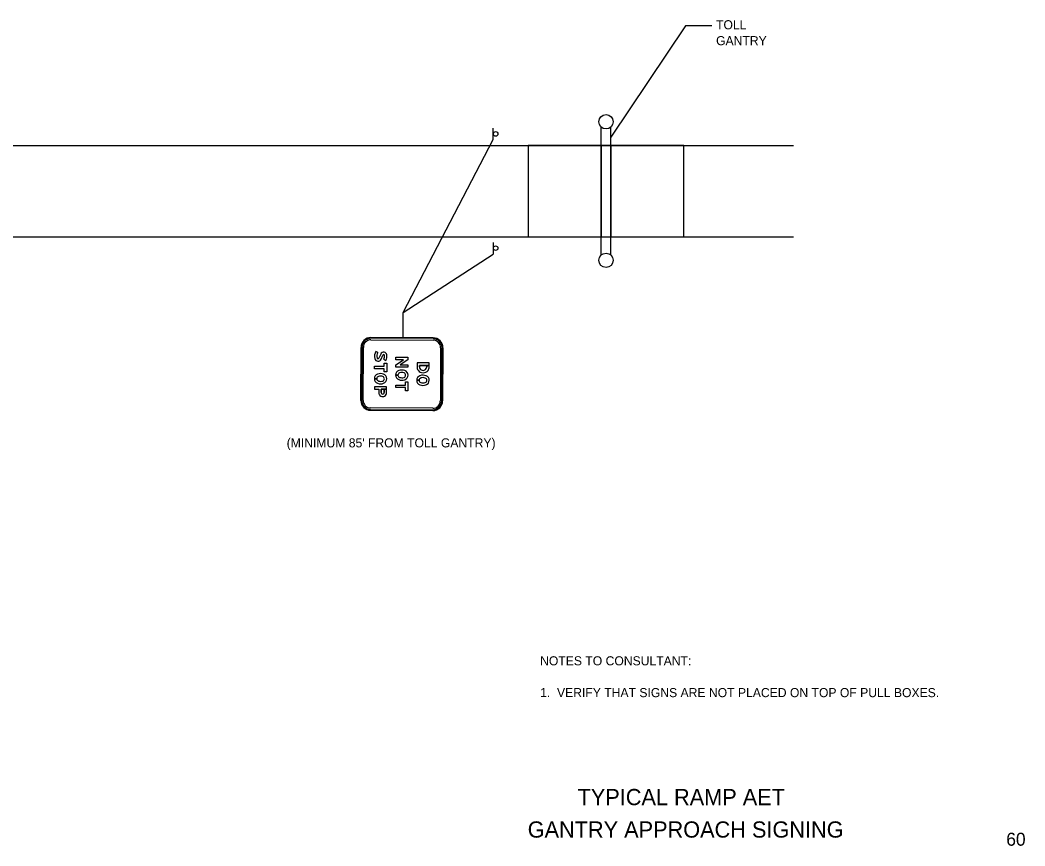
# Model space of a CAD drawing. Extents: x 2147219 to 2148785, y 2147055 to 2147716.
# Drawn here: x 2148011 to 2148785, y 2147080 to 2147716 of the extents above; entities that cross this region are included whole.
import ezdxf

# ---------------------------------------------------------------- set-up
doc = ezdxf.new("R2010")
doc.units = 0
for name, color, linetype in [('4', 7, 'Continuous'), ('5', 7, 'Continuous'), ('Default', 7, 'Continuous'), ('LeaderLine_dp', 7, 'Continuous'), ('RoadwayMisc', 7, 'Continuous'), ('SignPanel', 7, 'Continuous'), ('SignSupport', 7, 'Continuous'), ('TextMisc', 7, 'Continuous'), ('TextShtNo', 7, 'Continuous'), ('TollReader', 7, 'Continuous')]:
    doc.layers.add(name, color=color, linetype=linetype)

msp = doc.modelspace()

# ---------------------------------------------------------------- linework, layer by layer
at = {"layer": '4'}
msp.add_line((2148523.89, 2147711.93), (2148466.13, 2147626.09), dxfattribs=at)
at = {"layer": 'Default'}
msp.add_line((2148543.93, 2147711.93), (2148523.89, 2147711.93), dxfattribs=at)
at = {"layer": 'LeaderLine_dp'}
for p, q in [((2148306.25, 2147490.99), (2148375.7, 2147624.25)), ((2148306.25, 2147490.99), (2148375.7, 2147536.1)), ((2148306.15, 2147471.79), (2148306.25, 2147490.99))]:
    msp.add_line(p, q, dxfattribs=at)
at = {"layer": 'RoadwayMisc'}
for p, q in [((2147481.92, 2147619.77), (2148606.92, 2147619.77)), ((2148458.91, 2147619.77), (2148402.52, 2147619.77)), ((2148402.52, 2147619.77), (2148402.52, 2147549.46)), ((2148458.91, 2147549.46), (2148458.91, 2147619.77)), ((2148466.13, 2147619.77), (2148458.91, 2147619.77)), ((2148458.91, 2147619.77), (2148458.91, 2147549.46)), ((2148522.52, 2147619.77), (2148466.13, 2147619.77)), ((2148466.13, 2147619.77), (2148466.13, 2147549.46)), ((2148466.13, 2147549.46), (2148466.13, 2147619.77)), ((2148522.52, 2147549.46), (2148522.52, 2147619.77)), ((2147481.92, 2147549.46), (2148606.92, 2147549.46)), ((2148402.52, 2147549.46), (2148458.91, 2147549.46)), ((2148458.91, 2147549.46), (2148466.13, 2147549.46)), ((2148466.13, 2147549.46), (2148522.52, 2147549.46))]:
    msp.add_line(p, q, dxfattribs=at)
at = {"layer": 'SignPanel'}
for p, q in [((2148329.31, 2147471.48), (2148281.46, 2147471.71)), ((2148329.31, 2147471.48), (2148281.46, 2147471.71)), ((2148281.46, 2147471.59), (2148329.31, 2147471.36)), ((2148273.84, 2147464.16), (2148273.64, 2147423.32)), ((2148273.84, 2147464.16), (2148273.64, 2147423.32)), ((2148273.76, 2147423.32), (2148273.96, 2147464.16)), ((2148273.84, 2147464.16), (2148273.96, 2147464.16)), ((2148273.96, 2147464.16), (2148273.84, 2147464.16)), ((2148274.42, 2147464.15), (2148274.23, 2147423.31)), ((2148274.42, 2147464.16), (2148275.59, 2147464.16)), ((2148275.59, 2147464.14), (2148274.42, 2147464.15)), ((2148275.39, 2147423.31), (2148275.59, 2147464.14)), ((2148281.45, 2147469.96), (2148329.3, 2147469.73)), ((2148329.3, 2147470.9), (2148281.46, 2147471.13)), ((2148335.1, 2147463.87), (2148334.91, 2147423.02)), ((2148336.07, 2147423.02), (2148336.27, 2147463.86)), ((2148336.74, 2147463.86), (2148336.54, 2147423.01)), ((2148336.66, 2147423.01), (2148336.85, 2147463.86)), ((2148336.66, 2147423.01), (2148336.85, 2147463.86)), ((2148286.82, 2147460.12), (2148285.23, 2147461.09)), ((2148286.82, 2147460.12), (2148285.23, 2147461.09)), ((2148286.82, 2147460.12), (2148285.23, 2147461.09)), ((2148288.99, 2147458.99), (2148287.59, 2147455.83)), ((2148288.99, 2147458.99), (2148287.59, 2147455.83)), ((2148288.99, 2147458.99), (2148287.59, 2147455.83)), ((2148289.29, 2147455.08), (2148290.7, 2147458.23)), ((2148289.29, 2147455.08), (2148290.7, 2147458.23)), ((2148289.29, 2147455.08), (2148290.7, 2147458.23)), ((2148291.32, 2147454.99), (2148292.97, 2147454.1)), ((2148291.32, 2147454.99), (2148292.97, 2147454.1)), ((2148291.32, 2147454.99), (2148292.97, 2147454.1)), ((2148316.94, 2147449.12), (2148316.94, 2147449.12)), ((2148318.81, 2147449.11), (2148318.81, 2147450.3)), ((2148318.81, 2147449.11), (2148318.81, 2147450.3)), ((2148318.81, 2147449.11), (2148318.81, 2147449.11)), ((2148300.41, 2147442.82), (2148302.28, 2147442.81)), ((2148302.28, 2147442.81), (2148300.41, 2147442.82)), ((2148300.41, 2147442.82), (2148302.28, 2147442.81)), ((2148302.28, 2147442.81), (2148300.41, 2147442.82)), ((2148284.07, 2147440), (2148285.93, 2147440)), ((2148285.93, 2147440), (2148284.07, 2147440)), ((2148284.07, 2147440), (2148285.93, 2147440)), ((2148285.93, 2147440), (2148284.07, 2147440)), ((2148316.73, 2147438.82), (2148318.6, 2147438.81)), ((2148318.6, 2147438.81), (2148316.73, 2147438.82)), ((2148316.73, 2147438.82), (2148318.6, 2147438.81)), ((2148318.6, 2147438.81), (2148316.73, 2147438.82)), ((2148287.54, 2147431.99), (2148287.53, 2147429.22)), ((2148289.41, 2147431.98), (2148289.4, 2147429.31)), ((2148329.05, 2147417.22), (2148281.2, 2147417.45)), ((2148281.19, 2147416.28), (2148329.04, 2147416.05)), ((2148329.04, 2147415.58), (2148281.19, 2147415.81)), ((2148281.19, 2147415.7), (2148329.04, 2147415.47)), ((2148281.19, 2147415.7), (2148329.04, 2147415.47))]:
    msp.add_line(p, q, dxfattribs=at)
for points in [[(2148309.98, 2147456.49), (2148309.97, 2147454.63), (2148304.07, 2147450.83), (2148309.95, 2147450.8), (2148309.94, 2147448.93), (2148300.61, 2147448.98), (2148300.62, 2147450.82), (2148306.55, 2147454.64), (2148300.63, 2147454.67), (2148300.64, 2147456.54)], [(2148309.98, 2147456.49), (2148309.97, 2147454.63), (2148304.07, 2147450.83), (2148309.95, 2147450.8), (2148309.94, 2147448.93), (2148300.61, 2147448.98), (2148300.62, 2147450.82), (2148306.55, 2147454.64), (2148300.63, 2147454.67), (2148300.64, 2147456.54)], [(2148309.98, 2147456.49), (2148309.97, 2147454.63), (2148304.07, 2147450.83), (2148309.95, 2147450.8), (2148309.94, 2147448.93), (2148300.61, 2147448.98), (2148300.62, 2147450.82), (2148306.55, 2147454.64), (2148300.63, 2147454.67), (2148300.64, 2147456.54)], [(2148284.27, 2147447.75), (2148284.28, 2147449.62), (2148291.74, 2147449.58), (2148291.76, 2147452.1), (2148293.62, 2147452.09), (2148293.59, 2147445.19), (2148291.72, 2147445.19), (2148291.73, 2147447.71)], [(2148284.27, 2147447.75), (2148284.28, 2147449.62), (2148291.74, 2147449.58), (2148291.76, 2147452.1), (2148293.62, 2147452.09), (2148293.59, 2147445.19), (2148291.72, 2147445.19), (2148291.73, 2147447.71)], [(2148284.27, 2147447.75), (2148284.28, 2147449.62), (2148291.74, 2147449.58), (2148291.76, 2147452.1), (2148293.62, 2147452.09), (2148293.59, 2147445.19), (2148291.72, 2147445.19), (2148291.73, 2147447.71)], [(2148300.53, 2147433.2), (2148300.54, 2147435.07), (2148308.01, 2147435.04), (2148308.02, 2147437.56), (2148309.89, 2147437.55), (2148309.85, 2147430.64), (2148307.99, 2147430.65), (2148308, 2147433.17)], [(2148300.53, 2147433.2), (2148300.54, 2147435.07), (2148308.01, 2147435.04), (2148308.02, 2147437.56), (2148309.89, 2147437.55), (2148309.85, 2147430.64), (2148307.99, 2147430.65), (2148308, 2147433.17)], [(2148300.53, 2147433.2), (2148300.54, 2147435.07), (2148308.01, 2147435.04), (2148308.02, 2147437.56), (2148309.89, 2147437.55), (2148309.85, 2147430.64), (2148307.99, 2147430.65), (2148308, 2147433.17)]]:
    msp.add_lwpolyline(points, close=True, dxfattribs=at)
for points in [[(2148326.27, 2147449.07), (2148326.29, 2147452.12), (2148316.96, 2147452.17), (2148316.94, 2147449.12)], [(2148318.81, 2147450.3), (2148326.28, 2147450.27), (2148326.29, 2147452.12), (2148316.96, 2147452.17), (2148316.94, 2147449.12)], [(2148318.81, 2147450.3), (2148326.28, 2147450.27), (2148326.29, 2147452.12), (2148316.96, 2147452.17), (2148316.94, 2147449.12)], [(2148324.41, 2147449.08), (2148324.41, 2147450.28), (2148318.81, 2147450.3), (2148318.81, 2147449.11)], [(2148326.27, 2147449.07), (2148326.28, 2147450.27), (2148324.41, 2147450.28), (2148324.41, 2147449.08)], [(2148326.27, 2147449.07), (2148326.28, 2147450.27), (2148324.41, 2147450.28), (2148324.41, 2147449.08)], [(2148293.51, 2147429.19), (2148293.53, 2147433.8), (2148284.2, 2147433.84), (2148284.19, 2147432), (2148287.54, 2147431.99)], [(2148293.53, 2147433.8), (2148284.2, 2147433.84), (2148284.19, 2147432), (2148287.54, 2147431.99), (2148287.53, 2147429.22)], [(2148293.53, 2147433.8), (2148284.2, 2147433.84), (2148284.19, 2147432), (2148287.54, 2147431.99), (2148287.53, 2147429.22)], [(2148289.4, 2147429.31), (2148289.41, 2147431.98), (2148293.53, 2147431.96), (2148293.53, 2147433.8)], [(2148289.4, 2147429.31), (2148289.41, 2147431.98), (2148293.53, 2147431.96), (2148293.53, 2147433.8)], [(2148291.65, 2147429.29), (2148291.66, 2147431.97), (2148289.41, 2147431.98)], [(2148293.51, 2147429.19), (2148293.53, 2147431.96), (2148291.66, 2147431.97), (2148291.65, 2147429.29)], [(2148293.51, 2147429.19), (2148293.53, 2147431.96), (2148291.66, 2147431.97), (2148291.65, 2147429.29)]]:
    msp.add_lwpolyline(points, dxfattribs=at)
for centre, radius, start, end in [((2148281.42, 2147464.13), 7.58, 89.72459, 179.72459), ((2148281.42, 2147464.13), 7.58, 89.72459, 179.72459), ((2148281.42, 2147464.13), 7.47, 89.72459, 179.72459), ((2148281.42, 2147464.13), 7, 89.72459, 179.72459), ((2148281.42, 2147464.13), 5.83, 89.72459, 179.72459), ((2148329.27, 2147463.9), 7, 359.72459, 89.72459), ((2148329.27, 2147463.9), 5.83, 359.72459, 89.72459), ((2148329.27, 2147463.9), 7.58, 359.72459, 89.72459), ((2148329.27, 2147463.9), 7.58, 359.72459, 89.72459), ((2148329.27, 2147463.9), 7.47, 359.72459, 89.72459), ((2148291.43, 2147457.28), 7.28, 148.44393, 194.20211), ((2148291.43, 2147457.28), 7.28, 148.44393, 194.20211), ((2148291.43, 2147457.28), 7.28, 148.44393, 194.20211), ((2148291.43, 2147457.28), 5.41, 148.44392, 194.2021), ((2148291.43, 2147457.28), 5.41, 148.44392, 194.2021), ((2148291.43, 2147457.28), 5.41, 148.44392, 194.2021), ((2148291.25, 2147457.98), 2.47, 9.21225, 156.04888), ((2148291.25, 2147457.98), 2.47, 9.21225, 156.04888), ((2148291.25, 2147457.98), 2.47, 9.21225, 156.04888), ((2148291.25, 2147457.98), 0.607, 9.21225, 156.04888), ((2148291.25, 2147457.98), 0.607, 9.21225, 156.04888), ((2148291.25, 2147457.98), 0.607, 9.21225, 156.04888), ((2148287.06, 2147457.3), 4.85, 331.54595, 9.21225), ((2148287.06, 2147457.3), 4.85, 331.54595, 9.21225), ((2148287.06, 2147457.3), 4.85, 331.54595, 9.21225), ((2148287.06, 2147457.3), 6.72, 331.54595, 9.21225), ((2148287.06, 2147457.3), 6.72, 331.54595, 9.21225), ((2148287.06, 2147457.3), 6.72, 331.54595, 9.21225), ((2148286.91, 2147456.14), 2.61, 194.2021, 336.04888), ((2148286.91, 2147456.14), 2.61, 194.2021, 336.04888), ((2148286.91, 2147456.14), 2.61, 194.2021, 336.04888), ((2148286.91, 2147456.14), 0.747, 194.2021, 336.04888), ((2148286.91, 2147456.14), 0.747, 194.2021, 336.04888), ((2148286.91, 2147456.14), 0.747, 194.2021, 336.04888), ((2148304.15, 2147442.8), 3.73, 109.33085, 250.11834), ((2148304.15, 2147442.8), 3.73, 109.33085, 179.72459), ((2148304.15, 2147442.8), 3.73, 109.33085, 179.72459), ((2148304.15, 2147442.8), 3.73, 179.73175, 250.11834), ((2148304.15, 2147442.8), 3.73, 179.73175, 250.11834), ((2148304.15, 2147442.8), 1.87, 109.33085, 250.11834), ((2148304.15, 2147442.8), 1.87, 109.33085, 179.72459), ((2148304.15, 2147442.8), 1.87, 109.33085, 179.72459), ((2148304.15, 2147442.8), 1.87, 179.73892, 250.11834), ((2148304.15, 2147442.8), 1.87, 179.73892, 250.11834), ((2148305.21, 2147439.76), 6.95, 70.11834, 109.33084), ((2148305.21, 2147439.76), 6.95, 70.11834, 109.33085), ((2148305.21, 2147439.76), 6.95, 70.11834, 109.33085), ((2148305.24, 2147445.83), 5.09, 250.11834, 289.33084), ((2148305.24, 2147445.83), 5.09, 250.11834, 289.33084), ((2148305.24, 2147445.83), 5.09, 250.11834, 289.33084), ((2148305.21, 2147439.76), 5.09, 70.11834, 109.33084), ((2148305.21, 2147439.76), 5.09, 70.11834, 109.33084), ((2148305.21, 2147439.76), 5.09, 70.11834, 109.33084), ((2148306.31, 2147442.79), 1.87, 289.33085, 70.11834), ((2148306.31, 2147442.79), 1.87, 289.33085, 70.11834), ((2148306.31, 2147442.79), 1.87, 289.33085, 70.11834), ((2148306.31, 2147442.79), 3.73, 289.33085, 70.11834), ((2148306.31, 2147442.79), 3.73, 289.33084, 70.11834), ((2148306.31, 2147442.79), 3.73, 289.33084, 70.11834), ((2148305.24, 2147445.83), 6.95, 250.11834, 289.33084), ((2148305.24, 2147445.83), 6.95, 250.11834, 289.33085), ((2148305.24, 2147445.83), 6.95, 250.11834, 289.33085), ((2148281.23, 2147423.28), 7.58, 179.72459, 269.72459), ((2148281.23, 2147423.28), 7.58, 179.72459, 269.72459), ((2148281.23, 2147423.28), 7.47, 179.72459, 269.72459), ((2148281.23, 2147423.28), 7, 179.72459, 269.72459), ((2148281.23, 2147423.28), 5.83, 179.72459, 269.72459), ((2148329.07, 2147423.05), 7, 269.72459, 359.72459), ((2148329.07, 2147423.05), 7.58, 269.72459, 359.72459), ((2148329.07, 2147423.05), 7.47, 269.72459, 359.72459), ((2148329.07, 2147423.05), 7.58, 269.72459, 359.72459), ((2148329.07, 2147423.05), 5.83, 269.72459, 359.72459)]:
    msp.add_arc(centre, radius, start, end, dxfattribs=at)
for centre, major_axis, ratio, start_param, end_param in [((2148321.02, 2147448.98), (4.09, -0.02), 0.992015, 3.111301, 3.802985), ((2148321.02, 2147448.98), (4.09, -0.02), 0.992015, 3.111301, 3.802985), ((2148321.02, 2147448.98), (4.09, -0.02), 0.992015, 3.111301, 3.802985), ((2148321.33, 2147449.05), (2.53, -0.01), 0.992015, 3.123742, 3.672538), ((2148321.33, 2147449.05), (2.53, -0.01), 0.992015, 3.123742, 3.672538), ((2148321.33, 2147449.05), (2.53, -0.01), 0.992015, 3.123742, 3.672538), ((2148321.88, 2147449.05), (2.53, -0.01), 0.992015, 5.75224, 6.301036), ((2148321.88, 2147449.05), (2.53, -0.01), 0.992015, 5.75224, 6.301036), ((2148321.88, 2147449.05), (2.53, -0.01), 0.992015, 5.75224, 6.301036), ((2148322.19, 2147448.97), (4.09, -0.02), 0.992015, 5.621793, 6.313477), ((2148322.19, 2147448.97), (4.09, -0.02), 0.992015, 5.621793, 6.313477), ((2148322.19, 2147448.97), (4.09, -0.02), 0.992015, 5.621793, 6.313477), ((2148287.8, 2147439.99), (3.73, -0.02), 0.999998, 1.91299, 4.370195), ((2148287.8, 2147439.99), (3.73, -0.02), 0.999998, 1.91299, 3.141593), ((2148287.8, 2147439.99), (3.73, -0.02), 0.999998, 1.91299, 3.141593), ((2148287.8, 2147439.99), (1.87, -0.01), 0.999998, 1.91299, 4.370195), ((2148287.8, 2147439.99), (1.87, -0.01), 0.999998, 1.91299, 3.141593), ((2148287.8, 2147439.99), (1.87, -0.01), 0.999998, 1.91299, 3.141593), ((2148288.87, 2147436.95), (6.95, -0.03), 0.999998, 1.228603, 1.91299), ((2148288.87, 2147436.95), (6.95, -0.03), 0.999998, 1.228603, 1.91299), ((2148288.87, 2147436.95), (6.95, -0.03), 0.999998, 1.228603, 1.91299), ((2148288.87, 2147436.95), (5.09, -0.02), 0.999998, 1.228603, 1.91299), ((2148288.87, 2147436.95), (5.09, -0.02), 0.999998, 1.228603, 1.91299), ((2148288.87, 2147436.95), (5.09, -0.02), 0.999998, 1.228603, 1.91299), ((2148289.96, 2147439.98), (1.87, -0.01), 0.999998, 5.054583, 7.511788), ((2148289.96, 2147439.98), (1.87, -0.01), 0.999998, 5.054583, 7.511788), ((2148289.96, 2147439.98), (1.87, -0.01), 0.999998, 5.054583, 7.511788), ((2148289.96, 2147439.98), (3.73, -0.02), 0.999998, 5.054583, 7.511788), ((2148289.96, 2147439.98), (3.73, -0.02), 0.999998, 5.054583, 7.511788), ((2148289.96, 2147439.98), (3.73, -0.02), 0.999998, 5.054583, 7.511788), ((2148320.46, 2147438.8), (3.73, -0.02), 0.999996, 1.91299, 4.370195), ((2148320.46, 2147438.8), (3.73, -0.02), 0.999996, 1.91299, 3.141593), ((2148320.46, 2147438.8), (3.73, -0.02), 0.999996, 1.91299, 3.141593), ((2148321.56, 2147449.19), (4.65, -0.02), 0.992015, 3.769463, 4.722379), ((2148321.56, 2147449.19), (4.65, -0.02), 0.992015, 3.769463, 4.722379), ((2148321.56, 2147449.19), (4.65, -0.02), 0.992015, 3.769463, 4.722379), ((2148320.46, 2147438.8), (1.87, -0.01), 0.999996, 1.91299, 4.370195), ((2148320.46, 2147438.8), (1.87, -0.01), 0.999996, 1.91299, 3.141593), ((2148320.46, 2147438.8), (1.87, -0.01), 0.999996, 1.91299, 3.141593), ((2148321.54, 2147449.22), (2.79, -0.01), 0.992015, 3.689617, 4.738495), ((2148321.54, 2147449.22), (2.79, -0.01), 0.992015, 3.689617, 4.738495), ((2148321.54, 2147449.22), (2.79, -0.01), 0.992015, 3.689617, 4.738495), ((2148321.53, 2147435.76), (6.95, -0.03), 0.999996, 1.228603, 1.91299), ((2148321.53, 2147435.76), (6.95, -0.03), 0.999996, 1.228603, 1.91299), ((2148321.53, 2147435.76), (6.95, -0.03), 0.999996, 1.228603, 1.91299), ((2148321.53, 2147435.76), (5.09, -0.02), 0.999996, 1.228603, 1.91299), ((2148321.53, 2147435.76), (5.09, -0.02), 0.999996, 1.228603, 1.91299), ((2148321.53, 2147435.76), (5.09, -0.02), 0.999996, 1.228603, 1.91299), ((2148321.65, 2147449.19), (4.65, -0.02), 0.992015, 4.702399, 5.655315), ((2148321.65, 2147449.19), (4.65, -0.02), 0.992015, 4.702399, 5.655315), ((2148321.65, 2147449.19), (4.65, -0.02), 0.992015, 4.702399, 5.655315), ((2148321.68, 2147449.22), (2.79, -0.01), 0.992015, 4.686283, 5.735161), ((2148321.68, 2147449.22), (2.79, -0.01), 0.992015, 4.686283, 5.735161), ((2148321.68, 2147449.22), (2.79, -0.01), 0.992015, 4.686283, 5.735161), ((2148322.62, 2147438.79), (1.87, -0.01), 0.999996, 5.054583, 7.511788), ((2148322.62, 2147438.79), (1.87, -0.01), 0.999996, 5.054583, 7.511788), ((2148322.62, 2147438.79), (1.87, -0.01), 0.999996, 5.054583, 7.511788), ((2148322.62, 2147438.79), (3.73, -0.02), 0.999996, 5.054583, 7.511788), ((2148322.62, 2147438.79), (3.73, -0.02), 0.999996, 5.054583, 7.511788), ((2148322.62, 2147438.79), (3.73, -0.02), 0.999996, 5.054583, 7.511788), ((2148287.8, 2147439.99), (3.73, -0.02), 0.999998, 3.141718, 4.370195), ((2148287.8, 2147439.99), (3.73, -0.02), 0.999998, 3.141718, 4.370195), ((2148287.8, 2147439.99), (1.87, -0.01), 0.999998, 3.141843, 4.370195), ((2148287.8, 2147439.99), (1.87, -0.01), 0.999998, 3.141843, 4.370195), ((2148288.9, 2147443.01), (6.95, -0.03), 0.999998, 4.370195, 5.054583), ((2148288.9, 2147443.01), (6.95, -0.03), 0.999998, 4.370195, 5.054583), ((2148288.9, 2147443.01), (6.95, -0.03), 0.999998, 4.370195, 5.054583), ((2148288.9, 2147443.01), (5.09, -0.02), 0.999998, 4.370195, 5.054583), ((2148288.9, 2147443.01), (5.09, -0.02), 0.999998, 4.370195, 5.054583), ((2148288.9, 2147443.01), (5.09, -0.02), 0.999998, 4.370195, 5.054583), ((2148320.46, 2147438.8), (3.73, -0.02), 0.999996, 3.141718, 4.370195), ((2148320.46, 2147438.8), (3.73, -0.02), 0.999996, 3.141718, 4.370195), ((2148320.46, 2147438.8), (1.87, -0.01), 0.999996, 3.141843, 4.370195), ((2148320.46, 2147438.8), (1.87, -0.01), 0.999996, 3.141843, 4.370195), ((2148321.56, 2147441.83), (6.95, -0.03), 0.999996, 4.370195, 5.054583), ((2148321.56, 2147441.83), (6.95, -0.03), 0.999996, 4.370195, 5.054583), ((2148321.56, 2147441.83), (6.95, -0.03), 0.999996, 4.370195, 5.054583), ((2148321.56, 2147441.83), (5.09, -0.02), 0.999996, 4.370195, 5.054583), ((2148321.56, 2147441.83), (5.09, -0.02), 0.999996, 4.370195, 5.054583), ((2148321.56, 2147441.83), (5.09, -0.02), 0.999996, 4.370195, 5.054583), ((2148290.52, 2147429.2), (2.99, -0.01), 0.985873, 3.140988, 6.28379), ((2148290.52, 2147429.2), (2.99, -0.01), 0.985873, 3.140988, 6.28379), ((2148290.52, 2147429.2), (2.99, -0.01), 0.985873, 3.140988, 6.28379), ((2148290.52, 2147429.21), (1.13, -0.01), 0.985873, 3.056611, 6.368167), ((2148290.52, 2147429.21), (1.13, -0.01), 0.985873, 3.056611, 6.368167), ((2148290.52, 2147429.21), (1.13, -0.01), 0.985873, 3.056611, 6.368167)]:
    msp.add_ellipse(centre, major_axis=major_axis, ratio=ratio, start_param=start_param, end_param=end_param, dxfattribs=at)
at = {"layer": 'SignSupport'}
for p, q in [((2148375.7, 2147624.25), (2148375.7, 2147633.13)), ((2148375.71, 2147544.99), (2148375.7, 2147536.1))]:
    msp.add_line(p, q, dxfattribs=at)
for centre in [(2148377.52, 2147628.64), (2148377.52, 2147540.59)]:
    msp.add_circle(centre, 1.76, dxfattribs=at)
at = {"layer": 'TollReader'}
for p, q in [((2148458.91, 2147535.45), (2148458.91, 2147633.78)), ((2148466.13, 2147535.45), (2148466.13, 2147633.79))]:
    msp.add_line(p, q, dxfattribs=at)
for centre in [(2148462.52, 2147638), (2148462.52, 2147531.24)]:
    msp.add_circle(centre, 5.55, dxfattribs=at)

# ---------------------------------------------------------------- texts
at = {"layer": '5'}
for s, p in [('TOLL', (2148547.31, 2147709.26)), ('GANTRY', (2148547.31, 2147697.01)), ("(MINIMUM 85' FROM TOLL GANTRY)", (2148216.53, 2147387.08)), ('NOTES TO CONSULTANT:', (2148411.77, 2147219.12)), ('1.  VERIFY THAT SIGNS ARE NOT PLACED ON TOP OF PULL BOXES.', (2148411.77, 2147194.62))]:
    msp.add_text(s, height=7, dxfattribs=at).set_placement(p)
at = {"layer": 'TextMisc'}
for s, p in [('    TYPICAL RAMP AET    ', (2148422.05, 2147111.38)), ('GANTRY APPROACH SIGNING ', (2148402.2, 2147086.38))]:
    msp.add_text(s, height=12.5, rotation=360, dxfattribs=at).set_placement(p)
at = {"layer": 'TextShtNo'}
msp.add_text('60', height=10, rotation=360, dxfattribs=at).set_placement((2148770.87, 2147080.13))

doc.saveas('drawing.dxf')
